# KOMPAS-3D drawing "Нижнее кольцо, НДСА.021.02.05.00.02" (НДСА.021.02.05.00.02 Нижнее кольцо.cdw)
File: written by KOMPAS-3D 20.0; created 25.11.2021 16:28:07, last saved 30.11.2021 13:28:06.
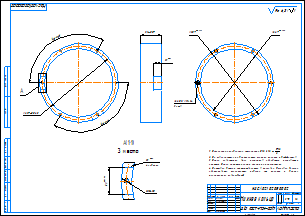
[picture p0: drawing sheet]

Sheet 1: A2, landscape

Document properties: Знак неуказанной шероховатости: 4; Параметр неуказанной шероховатости: Ra 6,3; PLM_CDWXDTO: <item xmlns="http://appius.ru/pdm" xmlns:xs="http://www.w3.org/2001/XMLSchema" xmlns:xsi="http://www.w3.org/2001/XMLSchema-instance" xsi:type="item">  <element xmlns:d2p1="http://v8.1c.ru/8.1/data/enterprise/current-config" xsi:type="d2p1:CatalogRef.aps_Элемен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; Масса: 3.75; PDM_DOCXDTO: <item xmlns="http://appius.ru/pdm" xmlns:xs="http://www.w3.org/2001/XMLSchema" xmlns:xsi="http://www.w3.org/2001/XMLSchema-instance" xsi:type="item">  <element xmlns:d2p1="http://v8.1c.ru/8.1/data/enterprise/current-config" xsi:type="d2p1:CatalogRef.aps_Элемен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; PDM_ITEMXDTO: <item xmlns="http://appius.ru/pdm" xmlns:xs="http://www.w3.org/2001/XMLSchema" xmlns:xsi="http://www.w3.org/2001/XMLSchema-instance" xsi:type="item">  <element xmlns:d2p1="http://v8.1c.ru/8.1/data/enterprise/current-config" xsi:type="d2p1:CatalogRef.aps_Элемен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; PDM_DRAWINGXDTO: <item xmlns="http://appius.ru/pdm" xmlns:xs="http://www.w3.org/2001/XMLSchema" xmlns:xsi="http://www.w3.org/2001/XMLSchema-instance" xsi:type="item">  <element xmlns:d2p1="http://v8.1c.ru/8.1/data/enterprise/current-config" xsi:type="d2p1:CatalogRef.aps_Элемен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

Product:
- Part/product: Нижнее кольцо  | designation НДСА.021.02.05.00.02
    Материал: Д16  ГОСТ 4784-2019 (density 2800 kg/m3)
    Масса: 3.75156
    additional columns: <item xmlns="http://appius.ru/pdm" xmlns:xs="http://www.w3.org/2001/XMLSchema" x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; <item xmlns="http://appius.ru/pdm" xmlns:xs="http://www.w3.org/2001/XMLSchema" x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; <item xmlns="http://appius.ru/pdm" xmlns:xs="http://www.w3.org/2001/XMLSchema" x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
    source file: НДСА.021.02.05.00.02 Нижнее кольцо.cdw

Title block, sheet 1: Наименование: Нижнее кольцо; designation: НДСА.021.02.05.00.02; Материал: Д16  ГОСТ 4784-2019; Масса: 3,75; Количество листов документа: 1; organisation: АО"НПП"ЭСТО"; Форматы листов документа: A2; stored path: C:\Users\korychko\Desktop\PLM\НДСА.021.02.05.00.02 Нижнее кольцо.cdw; Разработал: Корячко; Проверил: Горностаев; Утвердил: Белецкий; Разработал, date: 25.11.2021

Views: Вид 4, Вид:1, Проекционный вид 5, Проекционный вид 6, Выносной элемент 7, Выносной элемент А, Выносной элемент
Referenced files in C:\Users\korychko\Desktop\PLM\: НДСА.021.02.05.00.02 Нижнее кольцо.m3d
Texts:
  JS10
  JS9
  Ra 6,3
  Ra 6,3 ( )
  НДСА.021.02.05.00.02 Нижнее кольцо
Dimensions and other numbers on the sheet: 81±0,07; 31; 287±0,065; 120; 307; 267; 3 отв.; 52; -8H; 10; 3; 4 радиуса; 3 места; 1:2; 1; 3,75; 25.11.2021

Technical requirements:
  Неуказанные предельные отклонения H12, h12,    IT12 2 .
  На поверхностях не допускается наличие царапин и деффектов.
  После завершения всех процессов обработки произвести
  очистку. После очистки голыми руками не прикосаться.
  Поставка детали осуществляется в упаковке. Упаковка должна
  обеспечивать сохранность изделия от царапин и других
  механических повреждений.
